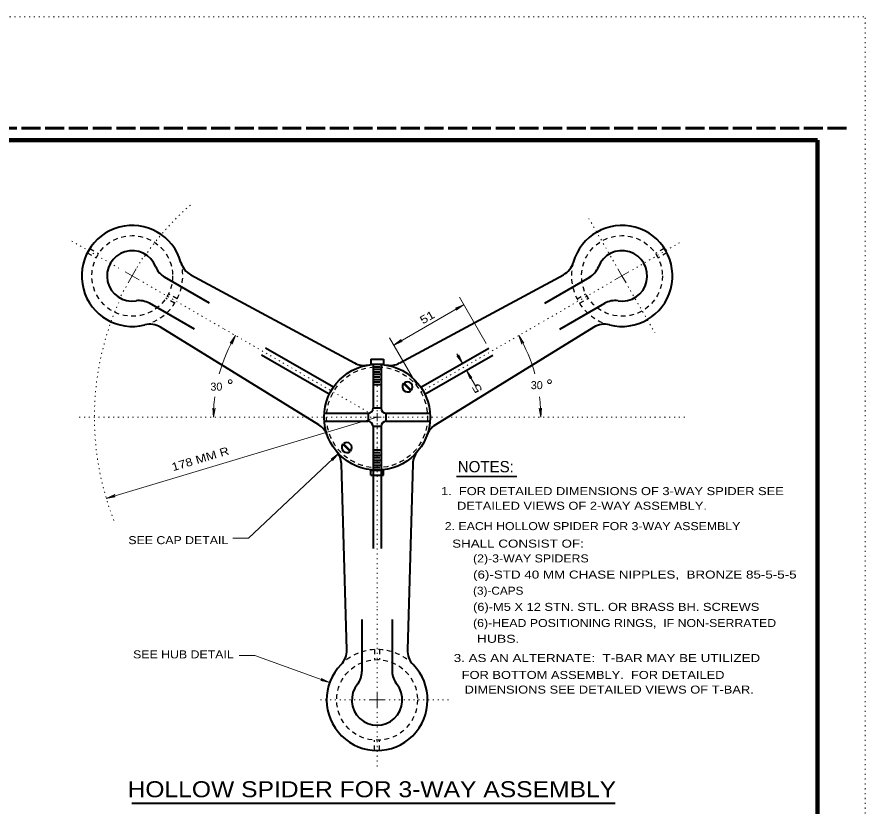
# Model space of a CAD drawing. Extents: x 312583 to 312854, y 144419 to 144597.
# Drawn here: x 312773 to 312853.5, y 144521.9 to 144596.8 of the extents above; entities that cross this region are included whole.
import ezdxf
from ezdxf.enums import TextEntityAlignment as Align

# ---------------------------------------------------------------- set-up
doc = ezdxf.new("R2010")
doc.units = 0
doc.header["$LTSCALE"] = 0.3
for name, pattern in [('DOTTED', [1.5, 0.3, -1.2]), ('LONG_DASHED', [7.5, 6, -1.5]), ('SHORT_DASHED', [2.7, 1.5, -1.2])]:
    doc.linetypes.add(name, pattern=pattern)
for name, color, linetype, lineweight in [('1', 7, 'Continuous', 40), ('2', 7, 'Continuous', 13), ('62', 7, 'DOTTED', 13), ('63', 7, 'LONG_DASHED', 60)]:
    doc.layers.add(name, color=color, linetype=linetype, lineweight=lineweight)

msp = doc.modelspace()

# ---------------------------------------------------------------- linework, layer by layer
at = {"layer": '1', "lineweight": 158}
msp.add_line((312849, 144423.1446), (312849, 144585.0846), dxfattribs=at)
at = {"layer": '1', "linetype": 'SHORT_DASHED', "lineweight": 25}
for p, q in [((312779.6873, 144574.3863), (312780.5229, 144573.9033)), ((312779.9326, 144574.8003), (312780.7606, 144574.3173)), ((312834.4503, 144574.8079), (312833.6223, 144574.3249)), ((312834.6956, 144574.3863), (312833.8599, 144573.9109)), ((312787.9749, 144569.6023), (312787.1469, 144570.0776)), ((312788.2203, 144570.0163), (312787.3846, 144570.4916)), ((312826.1703, 144570.0239), (312826.9983, 144570.4993)), ((312826.4079, 144569.6023), (312827.2359, 144570.0853)), ((312806.9576, 144536.7353), (312806.9576, 144535.7769)), ((312807.4329, 144536.7353), (312807.4329, 144535.7769)), ((312806.9576, 144527.1673), (312806.9576, 144528.1256)), ((312807.4329, 144527.1673), (312807.4329, 144528.1256))]:
    msp.add_line(p, q, dxfattribs=at)
at = {"layer": '1'}
for p, q in [((312791.2869, 144569.6253), (312787.0243, 144572.0939)), ((312789.5083, 144572.3163), (312805.0563, 144563.9366)), ((312809.3343, 144563.9366), (312824.8746, 144572.3163)), ((312823.0959, 144569.6253), (312827.3663, 144572.0939)), ((312789.8533, 144567.1413), (312785.5829, 144569.6023)), ((312824.5373, 144567.1413), (312828.7999, 144569.6023)), ((312801.6599, 144558.0639), (312786.6333, 144567.3329)), ((312827.7496, 144567.3329), (312812.7229, 144558.0639)), ((312803.0399, 144561.6289), (312796.5999, 144565.3473)), ((312811.3429, 144561.6289), (312817.7829, 144565.3473)), ((312802.6566, 144560.9619), (312796.2166, 144564.6803)), ((312811.7263, 144560.9619), (312818.1663, 144564.6803)), ((312806.5973, 144564.2969), (312807.7933, 144564.2969)), ((312806.8119, 144563.8216), (312806.8119, 144559.6509)), ((312806.9499, 144563.5763), (312807.4406, 144563.5763)), ((312807.5786, 144563.8216), (312807.5786, 144559.6509)), ((312807.7933, 144564.2969), (312807.7933, 144563.8216)), ((312806.8119, 144563.3386), (312807.5786, 144563.3386)), ((312806.8119, 144562.8633), (312807.5786, 144562.8633)), ((312806.9499, 144563.1009), (312807.4406, 144563.1009)), ((312806.8119, 144562.3803), (312807.5786, 144562.3803)), ((312806.9499, 144562.6179), (312807.4406, 144562.6179)), ((312806.9499, 144562.1426), (312807.4406, 144562.1426)), ((312810.3846, 144561.2993), (312809.7099, 144561.9739)), ((312810.4383, 144561.3529), (312809.7636, 144562.0276)), ((312806.8119, 144561.9049), (312807.5786, 144561.9049)), ((312807.5786, 144559.6509), (312806.8119, 144559.6509)), ((312802.1736, 144559.1756), (312806.3366, 144559.1756)), ((312806.3366, 144559.1756), (312806.3289, 144558.4089)), ((312808.0539, 144558.4013), (312808.0616, 144559.1679)), ((312808.0616, 144559.1679), (312812.2093, 144559.1679)), ((312802.1736, 144558.4089), (312806.3289, 144558.4089)), ((312806.8119, 144557.9259), (312806.8119, 144546.3339)), ((312806.8119, 144557.9259), (312807.5786, 144557.9259)), ((312807.5786, 144557.9259), (312807.5786, 144546.3339)), ((312808.0539, 144558.4013), (312812.2093, 144558.4013)), ((312803.9523, 144556.2163), (312804.6269, 144555.5416)), ((312804.0059, 144556.2699), (312804.6806, 144555.5953)), ((312806.8119, 144555.6796), (312807.5786, 144555.6796)), ((312806.8119, 144555.1966), (312807.5786, 144555.1966)), ((312806.8119, 144554.7213), (312807.5786, 144554.7213)), ((312806.9499, 144555.4419), (312807.4406, 144555.4419)), ((312806.9499, 144554.9589), (312807.4406, 144554.9589)), ((312804.3203, 144536.7046), (312803.7989, 144554.3609)), ((312806.8119, 144554.2383), (312807.5786, 144554.2383)), ((312806.9499, 144554.4836), (312807.4406, 144554.4836)), ((312806.9499, 144554.0006), (312807.4406, 144554.0006)), ((312810.5839, 144554.3609), (312810.0703, 144536.7046)), ((312806.5973, 144553.2799), (312807.7933, 144553.2799)), ((312807.7933, 144553.2799), (312807.7933, 144553.7629)), ((312805.7539, 144539.5949), (312805.7539, 144534.6653)), ((312808.6289, 144539.5949), (312808.6289, 144534.6653))]:
    msp.add_line(p, q, dxfattribs=at)
at = {"layer": '1', "linetype": 'DOTTED', "lineweight": 13}
for p, q in [((312811.3429, 144561.1843), (312822.7969, 144567.7929)), ((312806.3136, 144559.2906), (312792.6133, 144567.2026)), ((312807.1953, 144557.8263), (312807.1953, 144540.7679))]:
    msp.add_line(p, q, dxfattribs=at)
at = {"layer": '1', "lineweight": 158}
msp.add_lwpolyline([(312616.5, 144423.1446), (312616.5, 144585.0846), (312849, 144585.0846)], dxfattribs=at)
at = {"layer": '1'}
for points in [[(312806.5973, 144564.2969), (312806.5973, 144563.8216), (312807.7933, 144563.8216)], [(312806.5973, 144553.2799), (312806.5973, 144553.7629), (312807.7933, 144553.7629)]]:
    msp.add_lwpolyline(points, dxfattribs=at)
at = {"layer": '1', "linetype": 'SHORT_DASHED', "lineweight": 25}
for centre, radius in [((312783.9538, 144572.2013), 3.8333), ((312830.4291, 144572.2013), 3.8333), ((312807.1914, 144558.7846), 4.7917), ((312807.1914, 144531.9513), 3.8333)]:
    msp.add_circle(centre, radius, dxfattribs=at)
at = {"layer": '1'}
msp.add_circle((312807.1895, 144558.7846), 5.0312, dxfattribs=at)
at = {"layer": '1', "linetype": 'DOTTED', "lineweight": 13}
for start, end in [(131.33377, 145.44778), (155.02498, 201.77557)]:
    msp.add_arc((312807.1914, 144558.7846), 26.8333, start, end, dxfattribs=at)
at = {"layer": '1'}
for centre, radius, start, end in [((312783.9531, 144572.2013), 4.7917, 15.58331, 284.41669), ((312830.4298, 144572.2013), 4.7917, 255.58331, 164.41669), ((312783.9531, 144572.2013), 2.3958, 21.03954, 278.96046), ((312830.4298, 144572.2013), 2.3958, 261.03954, 158.96046), ((312790.415, 144574.0026), 1.9167, 195.57624, 241.68173), ((312823.9678, 144574.0026), 1.9167, 298.31827, 344.42376), ((312787.9776, 144573.7508), 1.9167, 201.05756, 240), ((312826.4053, 144573.7508), 1.9167, 300, 338.94244), ((312784.6234, 144567.9412), 1.9167, 60, 98.94244), ((312829.7594, 144567.9412), 1.9167, 81.05756, 120), ((312785.6241, 144565.7044), 1.9167, 58.31827, 104.42376), ((312828.7588, 144565.7044), 1.9167, 75.57624, 121.68173), ((312805.9629, 144565.6245), 1.9167, 241.68235, 280.19234), ((312808.4199, 144565.6245), 1.9167, 259.80766, 298.31765), ((312810.0703, 144561.6634), 0.4792, 139.54804, 310.45196), ((312810.0703, 144561.6634), 0.4792, 319.54804, 130.45196), ((312806.3328, 144559.6509), 0.4792, 270, 0), ((312808.0578, 144559.6471), 0.4792, 180, 270), ((312800.6536, 144556.4285), 1.9167, 19.80766, 58.31765), ((312806.3289, 144557.9259), 0.4792, 0, 90), ((312808.0539, 144557.9221), 0.4792, 90, 180), ((312813.7292, 144556.4285), 1.9167, 121.68235, 160.19234), ((312804.3126, 144555.9058), 0.4792, 319.54804, 130.45196), ((312801.8821, 144554.3007), 1.9167, 1.68235, 40.19234), ((312804.3126, 144555.9058), 0.4792, 139.54804, 310.45196), ((312812.5007, 144554.3007), 1.9167, 139.80766, 178.31765), ((312802.4005, 144536.6468), 1.9167, 315.57624, 1.68173), ((312811.9824, 144536.6468), 1.9167, 178.31827, 224.42376), ((312807.1914, 144531.9513), 4.7917, 135.58331, 44.41669), ((312803.8373, 144534.6618), 1.9167, 321.05756, 0), ((312810.5456, 144534.6618), 1.9167, 180, 218.94244), ((312807.1914, 144531.9513), 2.3958, 141.03954, 38.96046)]:
    msp.add_arc(centre, radius, start, end, dxfattribs=at)
at = {"layer": '1', "linetype": 'SHORT_DASHED', "lineweight": 25}
for centre, start, end in [((312783.9531, 144572.2013), 284.41669, 15.58331), ((312830.4298, 144572.2013), 164.41669, 255.58331), ((312807.1914, 144531.9513), 44.41669, 135.58331)]:
    msp.add_arc(centre, 4.7917, start, end, dxfattribs=at)
at = {"layer": '2', "linetype": 'DOTTED'}
for p, q in [((312829.8579, 144573.1979), (312827.2359, 144577.7443)), ((312782.6926, 144572.9296), (312778.2306, 144575.5056)), ((312831.4296, 144572.7763), (312836.1139, 144575.4826)), ((312784.4176, 144573.0063), (312785.0233, 144574.0566)), ((312784.9543, 144571.6263), (312792.6133, 144567.2026)), ((312829.4363, 144571.6263), (312822.7969, 144567.7929)), ((312783.3826, 144571.2046), (312782.7769, 144570.1619)), ((312831.0079, 144571.2046), (312833.5456, 144566.8116)), ((312807.1953, 144559.3596), (312807.1953, 144563.1929)), ((312806.6203, 144558.7846), (312778.7749, 144558.7846)), ((312807.7703, 144558.7846), (312836.6429, 144558.7846)), ((312807.1953, 144558.2096), (312807.1953, 144554.3763)), ((312807.1953, 144533.1013), (312807.1953, 144540.7679)), ((312806.0453, 144531.9513), (312801.5143, 144531.9513)), ((312808.3453, 144531.9513), (312814.1183, 144531.9513)), ((312807.1953, 144530.8013), (312807.1953, 144525.4883))]:
    msp.add_line(p, q, dxfattribs=at)
at = {"layer": '2'}
for p, q in [((312783.9576, 144572.2013), (312783.2906, 144572.5846)), ((312783.9576, 144572.2013), (312784.3409, 144572.8683)), ((312830.4329, 144572.2013), (312830.0496, 144572.8683)), ((312830.4329, 144572.2013), (312831.0923, 144572.5846)), ((312783.9576, 144572.2013), (312783.5743, 144571.5419)), ((312783.9576, 144572.2013), (312784.6169, 144571.8179)), ((312830.4329, 144572.2013), (312829.7659, 144571.8179)), ((312830.4329, 144572.2013), (312830.8163, 144571.5419)), ((312817.5376, 144565.7843), (312815.0076, 144570.1696)), ((312808.7669, 144565.6386), (312815.4063, 144569.4719)), ((312815.4063, 144569.4719), (312814.6013, 144569.1269)), ((312815.4063, 144569.4719), (312814.7086, 144568.9429)), ((312814.6013, 144569.1269), (312814.9003, 144569.1729)), ((312814.7086, 144568.9429), (312814.9003, 144569.1729)), ((312793.7403, 144566.5509), (312793.2573, 144565.8226)), ((312793.2573, 144565.8226), (312793.4719, 144566.0219)), ((312793.7403, 144566.5509), (312793.4489, 144565.7306)), ((312793.4489, 144565.7306), (312793.4719, 144566.0219)), ((312810.9519, 144561.8589), (312808.3683, 144566.3363)), ((312808.7669, 144565.6386), (312809.4646, 144566.1599)), ((312808.7669, 144565.6386), (312809.5719, 144565.9759)), ((312809.4646, 144566.1599), (312809.2806, 144565.9299)), ((312809.5719, 144565.9759), (312809.2806, 144565.9299)), ((312820.6426, 144566.5509), (312821.1333, 144565.8226)), ((312820.6426, 144566.5509), (312820.9416, 144565.7306)), ((312821.1333, 144565.8226), (312820.9109, 144566.0219)), ((312820.9416, 144565.7306), (312820.9109, 144566.0219)), ((312814.7623, 144564.6036), (312814.9923, 144564.4196)), ((312815.2913, 144563.9059), (312814.7623, 144564.6036)), ((312815.2913, 144563.9059), (312814.7699, 144564.8183)), ((312814.9539, 144564.7109), (312814.9923, 144564.4196)), ((312815.2913, 144563.9059), (312814.9539, 144564.7109)), ((312816.5179, 144561.7746), (312815.6746, 144563.2389)), ((312815.6746, 144563.2389), (312816.0119, 144562.4339)), ((312815.6746, 144563.2389), (312816.1959, 144562.5413)), ((312816.0119, 144562.4339), (312815.9659, 144562.7329)), ((312816.1959, 144562.5413), (312815.9659, 144562.7329)), ((312791.6013, 144559.6586), (312791.6933, 144559.3749)), ((312791.6626, 144558.7846), (312791.6013, 144559.6586)), ((312791.6626, 144558.7846), (312791.8159, 144559.6433)), ((312791.8159, 144559.6433), (312791.6933, 144559.3749)), ((312822.5669, 144559.6433), (312822.6896, 144559.3749)), ((312822.7203, 144558.7846), (312822.5669, 144559.6433)), ((312822.7816, 144559.6586), (312822.6896, 144559.3749)), ((312822.7203, 144558.7846), (312822.7816, 144559.6586)), ((312807.1953, 144558.7846), (312781.4889, 144551.0873)), ((312807.1953, 144558.7846), (312806.8119, 144558.7846)), ((312807.1953, 144558.7846), (312807.1953, 144559.1679)), ((312807.1953, 144558.7846), (312807.1953, 144558.4013)), ((312807.1953, 144558.7846), (312807.5786, 144558.7846)), ((312803.5306, 144555.3346), (312794.9746, 144547.2923)), ((312803.5306, 144555.3346), (312802.8253, 144554.8209)), ((312802.8253, 144554.8209), (312803.1013, 144554.9283)), ((312803.5306, 144555.3346), (312802.9709, 144554.6676)), ((312802.9709, 144554.6676), (312803.1013, 144554.9283)), ((312781.4889, 144551.0873), (312782.2863, 144551.4399)), ((312781.4889, 144551.0873), (312782.3476, 144551.2329)), ((312782.2863, 144551.4399), (312782.0563, 144551.2559)), ((312782.3476, 144551.2329), (312782.0563, 144551.2559)), ((312794.9746, 144547.2923), (312793.4949, 144547.2923)), ((312795.5726, 144536.1833), (312794.0929, 144536.1833)), ((312802.6873, 144533.5919), (312795.5726, 144536.1833)), ((312801.8363, 144533.7836), (312802.1353, 144533.7913)), ((312802.6873, 144533.5919), (312801.8363, 144533.7836)), ((312801.9129, 144533.9906), (312802.1353, 144533.7913)), ((312802.6873, 144533.5919), (312801.9129, 144533.9906)), ((312807.1953, 144531.9513), (312807.1953, 144532.7179)), ((312807.1953, 144531.9513), (312806.4286, 144531.9513)), ((312807.1953, 144531.9513), (312807.9619, 144531.9513)), ((312807.1953, 144531.9513), (312807.1953, 144531.1846))]:
    msp.add_line(p, q, dxfattribs=at)
at = {"layer": '2', "lineweight": 35}
msp.add_line((312814.7239, 144553.1472), (312820.4553, 144553.1472), dxfattribs=at)
at = {"layer": '2', "lineweight": 40}
msp.add_line((312783.9232, 144522.1534), (312829.7885, 144522.1534), dxfattribs=at)
at = {"layer": '2'}
for centre in [(312793.2532, 144562.1655), (312823.5519, 144562.1655)]:
    msp.add_circle(centre, 0.1798, dxfattribs=at)
for start, end in [(150.01129, 164.62993), (15.37008, 29.98871), (172.87872, 180), (0, 7.12128)]:
    msp.add_arc((312807.1914, 144558.7846), 15.5301, start, end, dxfattribs=at)
at = {"layer": '62'}
msp.add_line((312601.2, 144596.7846), (312853.5, 144596.7846), dxfattribs=at)
msp.add_lwpolyline([(312601.2, 144418.5846), (312853.5, 144418.5846), (312853.5, 144596.7846)], dxfattribs=at)
at = {"layer": '63'}
msp.add_line((312851.75, 144586.2246), (312583.526, 144586.2246), dxfattribs=at)

# ---------------------------------------------------------------- texts
at = {"layer": '2'}
for s, rotation, width, p in [('51', 30.001, 1.25, (312811.5282, 144567.5908)), ('5 ', 120, 1.5, (312817.2231, 144561.3398)), ('178 MM R', 16.669, 1.2, (312787.8239, 144553.6636))]:
    msp.add_text(s, height=0.76, rotation=rotation, dxfattribs=dict(at, width=width)).set_placement(p)
for p in [(312791.3732, 144561.3122), (312821.7781, 144561.4541)]:
    msp.add_text('30', height=0.76, dxfattribs=at).set_placement(p)
msp.add_text('NOTES:', height=1.07, dxfattribs=at).set_placement((312817.509, 144553.5618), align=Align.CENTER)
for s, width, p in [('1.  FOR DETAILED DIMENSIONS OF 3-WAY SPIDER SEE', 1.2, (312813.2596, 144551.3948)), ('  DETAILED VIEWS OF 2-WAY ASSEMBLY.', 1.2, (312814.1022, 144550.0034)), ('2. EACH HOLLOW SPIDER FOR 3-WAY ASSEMBLY', 1.15, (312813.6139, 144548.0714)), ('SEE CAP DETAIL', 1.15, (312783.5832, 144546.7397)), ('   SHALL CONSIST OF:', 1.25, (312813.2587, 144546.4115)), ('(2)-3-WAY SPIDERS', 1.15, (312816.2972, 144545.0048)), ('(6)-STD 40 MM CHASE NIPPLES,  BRONZE 85-5-5-5', 1.25, (312816.2972, 144543.4714)), ('(3)-CAPS', 1.1, (312816.2972, 144541.9381)), ('(6)-M5 X 12 STN. STL. OR BRASS BH. SCREWS', 1.2, (312816.2972, 144540.4048)), ('(6)-HEAD POSITIONING RINGS,  IF NON-SERRATED', 1.15, (312816.2972, 144538.8714)), ('    HUBS.', 1.3, (312815.1932, 144537.3764)), ('SEE HUB DETAIL', 1.15, (312784.0334, 144535.8953)), ('3. AS AN ALTERNATE:  T-BAR MAY BE UTILIZED', 1.25, (312814.4643, 144535.548)), ('   FOR BOTTOM ASSEMBLY.  FOR DETAILED', 1.2, (312814.207, 144533.9438)), ('  DIMENSIONS SEE DETAILED VIEWS OF T-BAR.', 1.2, (312814.8186, 144532.5523))]:
    msp.add_text(s, height=0.76, dxfattribs=dict(at, width=width)).set_placement(p)
at = {"layer": '2', "width": 1.15}
msp.add_text('HOLLOW SPIDER FOR 3-WAY ASSEMBLY', height=1.52, dxfattribs=at).set_placement((312806.6904, 144522.7141), align=Align.CENTER)

doc.saveas('drawing.dxf')
